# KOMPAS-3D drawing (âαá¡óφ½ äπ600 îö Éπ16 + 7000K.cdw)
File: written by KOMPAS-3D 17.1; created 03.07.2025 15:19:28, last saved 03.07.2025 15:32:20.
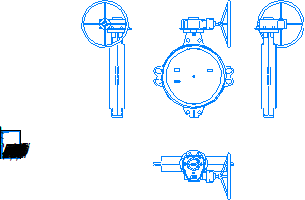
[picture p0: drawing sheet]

Sheet 1: A4, portrait

Title block, sheet 1: name: FL(W)-600-C-rev2- / PN16; material: Сталь 10  ГОСТ 1050-88; mass: 216,18; sheets: 1; sheet format: A4; stored path: \\adlc.lan\data\АДЛ_ПКД\3D-модели\ADL production\Дисковые поворотные затворы ГРАНВЭЛ\межфланцевый с китайским редуктором Ру16\KOMPAS 2D\Гранвэл Ду600 МФ Ру16 + 7000K.cdw

Views: Проекционный вид 2, Проекционный вид 3, Проекционный вид 4
Referenced files in \\adlc.lan\data\АДЛ_ПКД\3D-модели\ADL production\Дисковые поворотные затворы ГРАНВЭЛ\межфланцевый с китайским редуктором Ру16\KOMPAS 3D\: Гранвэл Ду600 МФ Ру16 + 7000K.m3d
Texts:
  Andrey
  АДЛ
Dimensions and other numbers on the sheet: 1:1; 1; 216,18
